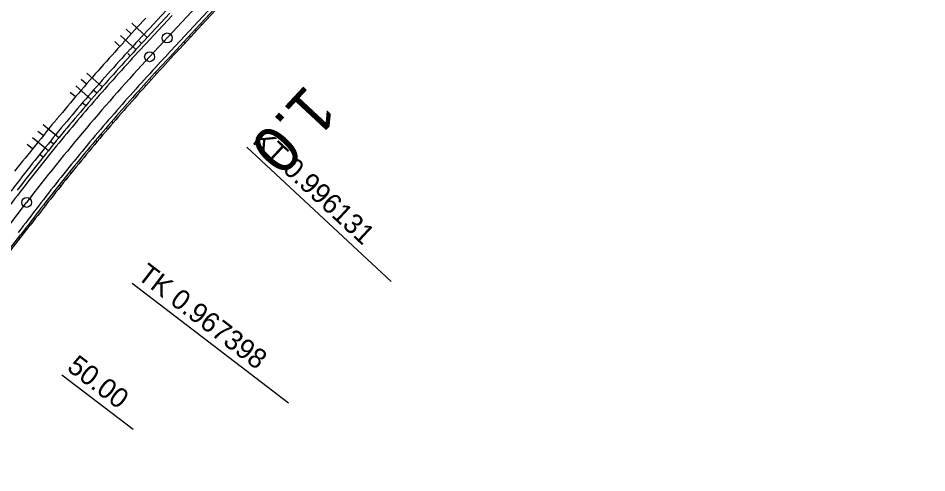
# Model space of a CAD drawing. Extents: x -481645 to -478728, y -1113199 to -1110710.
# Drawn here: x -479251.7 to -479114.8, y -1111118.3 to -1111049.8 of the extents above; entities that cross this region are included whole.
import ezdxf

# ---------------------------------------------------------------- set-up
doc = ezdxf.new("R2010")
doc.units = 0
for name, color, linetype in [('CP14_HATCH_SLOPE_L', 7, 'Continuous'), ('CP1_HECTOMETRY', 7, 'Continuous'), ('O6_HATCH_SLOPE_L', 7, 'Continuous'), ('O6_HATCH_SLOPE_R', 7, 'Continuous'), ('O6_HECTOMETRY', 7, 'Continuous'), ('O6_HLBODY', 7, 'Continuous'), ('O6_HRANA_TELESO', 7, 'Continuous'), ('O6_OSA', 7, 'Continuous'), ('O6_VOZOVKA', 7, 'Continuous'), ('O6_ZPEVKRAJ', 7, 'Continuous')]:
    doc.layers.add(name, color=color, linetype=linetype)

msp = doc.modelspace()

# ---------------------------------------------------------------- linework, layer by layer
at = {"layer": 'CP14_HATCH_SLOPE_L'}
for p, q in [((-479224.18, -1111050.66), (-479224, -1111050.83)), ((-479225.88, -1111052.49), (-479225.7, -1111052.67)), ((-479225.03, -1111051.57), (-479224.94, -1111051.66)), ((-479224.85, -1111051.75), (-479224.85, -1111051.75)), ((-479226.73, -1111053.41), (-479226.64, -1111053.49)), ((-479226.54, -1111053.58), (-479226.54, -1111053.58)), ((-479230.98, -1111057.98), (-479230.78, -1111058.16)), ((-479231.82, -1111058.89), (-479231.72, -1111058.98)), ((-479231.62, -1111059.08), (-479231.62, -1111059.08)), ((-479232.66, -1111059.81), (-479232.45, -1111060)), ((-479233.49, -1111060.73), (-479233.39, -1111060.82)), ((-479233.28, -1111060.92), (-479233.28, -1111060.92)), ((-479237.59, -1111065.38), (-479237.37, -1111065.57)), ((-479239.21, -1111067.27), (-479238.98, -1111067.46)), ((-479238.4, -1111066.32), (-479238.29, -1111066.42)), ((-479238.17, -1111066.52), (-479238.17, -1111066.52)), ((-479240.01, -1111068.21), (-479239.89, -1111068.31)), ((-479239.78, -1111068.41), (-479239.78, -1111068.41)), ((-479243.95, -1111073), (-479243.72, -1111073.19)), ((-479244.73, -1111073.97), (-479244.61, -1111074.06)), ((-479244.5, -1111074.15), (-479244.5, -1111074.15)), ((-479245.5, -1111074.94), (-479245.27, -1111075.12)), ((-479246.27, -1111075.91), (-479246.16, -1111076)), ((-479246.04, -1111076.09), (-479246.04, -1111076.09)), ((-479250.07, -1111080.84), (-479249.86, -1111081)), ((-479250.83, -1111081.83), (-479250.73, -1111081.91)), ((-479250.62, -1111081.99), (-479250.62, -1111081.99)), ((-479251.59, -1111082.82), (-479251.39, -1111082.98))]:
    msp.add_line(p, q, dxfattribs=at)
at = {"layer": 'CP1_HECTOMETRY'}
for p, q in [((-479231.87, -1111055.62), (-478997.26, -1110803.33)), ((-479472.65, -1111367.92), (-479250.4, -1111077.57))]:
    msp.add_line(p, q, dxfattribs=at)
msp.add_arc((-479012.18, -1111259.92), 300, 137.0793, 142.5669, dxfattribs=at)
at = {"layer": 'O6_HATCH_SLOPE_L'}
msp.add_circle((-479229.23, -1111052.79), 0.75, dxfattribs=at)
at = {"layer": 'O6_HATCH_SLOPE_R'}
for p, q in [((-479232.24, -1111052.71), (-479234.56, -1111050.55)), ((-479233.94, -1111054.55), (-479236.26, -1111052.4)), ((-479234.62, -1111052.2), (-479235.41, -1111051.47)), ((-479236.34, -1111054.06), (-479237.12, -1111053.34)), ((-479233.09, -1111053.63), (-479233.46, -1111053.28)), ((-479234.8, -1111055.48), (-479235.17, -1111055.13)), ((-479241.39, -1111059.75), (-479242.18, -1111059.06)), ((-479239.01, -1111060.16), (-479241.35, -1111058.1)), ((-479240.67, -1111062.05), (-479243.01, -1111060.02)), ((-479243.05, -1111061.67), (-479243.84, -1111060.99)), ((-479239.84, -1111061.1), (-479240.22, -1111060.77)), ((-479241.49, -1111063.01), (-479241.87, -1111062.68)), ((-479245.54, -1111067.83), (-479247.9, -1111065.88)), ((-479247.92, -1111067.51), (-479248.71, -1111066.87)), ((-479249.51, -1111069.49), (-479250.31, -1111068.85)), ((-479247.13, -1111069.78), (-479249.51, -1111067.85)), ((-479246.34, -1111068.8), (-479246.73, -1111068.48)), ((-479247.92, -1111070.76), (-479248.32, -1111070.44))]:
    msp.add_line(p, q, dxfattribs=at)
at = {"layer": 'O6_HECTOMETRY'}
for p, q in [((-479217.22, -1111069.24), (-479195.47, -1111089.47)), ((-479234.52, -1111089.72), (-479210.93, -1111107.78))]:
    msp.add_line(p, q, dxfattribs=at)
for centre in [(-479231.87, -1111055.62), (-479250.4, -1111077.57)]:
    msp.add_circle(centre, 0.75, dxfattribs=at)
at = {"layer": 'O6_HLBODY'}
msp.add_line((-479245.09, -1111103.54), (-479234.37, -1111111.74), dxfattribs=at)
at = {"layer": 'O6_HRANA_TELESO'}
msp.add_line((-479231.37, -1111050.8), (-479227.97, -1111047.14), dxfattribs=at)
for centre, radius, start, end in [((-479122.13, -1111155.72), 151.46, 136.156, 138.0517), ((-479012.18, -1111259.92), 302.92, 137.2952, 138.2501), ((-479012.18, -1111259.92), 302.92, 138.2501, 139.2051), ((-479012.18, -1111259.92), 302.92, 139.2051, 140.16), ((-479012.18, -1111259.92), 302.92, 140.16, 141.1149), ((-479012.18, -1111259.92), 302.92, 141.1149, 142.0699), ((-478532.29, -1111629.71), 908.75, 142.27851, 142.59535)]:
    msp.add_arc(centre, radius, start, end, dxfattribs=at)
at = {"layer": 'O6_OSA'}
for p, q in [((-479224, -1111050.83), (-479220.6, -1111047.16)), ((-479227.39, -1111054.5), (-479224, -1111050.83)), ((-479252.91, -1111084.96), (-479249.86, -1111081))]:
    msp.add_line(p, q, dxfattribs=at)
for centre, radius, start, end in [((-479122.26, -1111154.77), 152.18, 136.3891, 138.2779), ((-479011.31, -1111258.96), 304.34, 137.5391, 138.4941), ((-479119.92, -1111157.32), 148.74, 136.2679, 138.1904), ((-479011.26, -1111258.86), 304.32, 138.5136, 139.4685), ((-479011.66, -1111259.34), 297.47, 137.4446, 138.3995), ((-479011.43, -1111259.03), 304.3, 139.4246, 140.3796), ((-479011.83, -1111259.52), 297.46, 138.3527, 139.3077), ((-479011.62, -1111259.23), 304.28, 140.3274, 141.2824), ((-479011.84, -1111259.51), 297.45, 139.3068, 140.2618), ((-479013.18, -1111261.17), 304.29, 140.814, 141.769), ((-479012.45, -1111260.25), 297.45, 140.0777, 141.0327), ((-479012.75, -1111260.64), 297.46, 140.9378, 141.8927), ((-478543, -1111625.73), 892.4, 142.06107, 142.38068)]:
    msp.add_arc(centre, radius, start, end, dxfattribs=at)
at = {"layer": 'O6_VOZOVKA'}
for p, q in [((-479225.9, -1111051.78), (-479222.5, -1111048.11)), ((-479231.87, -1111053.05), (-479228.47, -1111049.39)), ((-479229.31, -1111055.44), (-479225.9, -1111051.78))]:
    msp.add_line(p, q, dxfattribs=at)
for centre, radius, start, end in [((-479122.77, -1111157.27), 150.88, 136.313, 138.2188), ((-479121.48, -1111158.45), 149.12, 136.308, 138.2221), ((-479012.18, -1111259.92), 301.75, 137.6756, 138.6306), ((-479012.18, -1111259.92), 298.25, 137.6756, 138.6306), ((-479012.18, -1111259.92), 301.75, 138.6306, 139.5855), ((-479012.18, -1111259.92), 298.25, 138.6306, 139.5855), ((-479012.18, -1111259.92), 301.75, 139.5855, 140.5404), ((-479012.18, -1111259.92), 298.25, 139.5855, 140.5404), ((-479012.18, -1111259.92), 301.75, 140.5404, 141.4954), ((-479012.18, -1111259.92), 298.25, 140.5404, 141.4954), ((-479012.18, -1111259.92), 301.75, 141.4954, 142.4503), ((-479012.18, -1111259.92), 298.25, 141.4954, 142.4503), ((-478534.18, -1111628.33), 905.25, 142.40137, 142.71806), ((-478539.74, -1111624.08), 894.75, 142.39981, 142.71976)]:
    msp.add_arc(centre, radius, start, end, dxfattribs=at)
at = {"layer": 'O6_ZPEVKRAJ'}
for p, q in [((-479232.24, -1111052.71), (-479228.83, -1111049.05)), ((-479225.54, -1111052.12), (-479222.13, -1111048.46)), ((-479228.94, -1111055.78), (-479225.54, -1111052.12)), ((-479254.32, -1111086.39), (-479251.28, -1111082.42))]:
    msp.add_line(p, q, dxfattribs=at)
for centre, radius, start, end in [((-479122.95, -1111157.1), 151.12, 136.3137, 138.2183), ((-479012.18, -1111259.92), 302.25, 137.6756, 138.6306), ((-479121.3, -1111158.62), 148.88, 136.3073, 138.2226), ((-479012.18, -1111259.92), 302.25, 138.6306, 139.5855), ((-479012.18, -1111259.92), 297.75, 137.6756, 138.6306), ((-479012.18, -1111259.92), 297.75, 138.6306, 139.5855), ((-479012.18, -1111259.92), 302.25, 139.5855, 140.5404), ((-479012.18, -1111259.92), 297.75, 139.5855, 140.5404), ((-479012.18, -1111259.92), 302.25, 140.5404, 141.4954), ((-479012.18, -1111259.92), 297.75, 140.5404, 141.4954), ((-479012.18, -1111259.92), 302.25, 141.4954, 142.4503), ((-479012.18, -1111259.92), 297.75, 141.4954, 142.4503), ((-478540.53, -1111623.47), 893.25, 142.39959, 142.72001)]:
    msp.add_arc(centre, radius, start, end, dxfattribs=at)

# ---------------------------------------------------------------- texts
at = {"layer": 'O6_HATCH_SLOPE_L'}
msp.add_text('1.0', height=7, rotation=227.0337, dxfattribs=at).set_placement((-479208.24, -1111059.59))
at = {"layer": 'O6_HECTOMETRY'}
for s, rotation, p in [('KT 0.996131', 317.0793, (-479216.54, -1111068.51)), ('TK 0.967398', 322.5669, (-479233.91, -1111088.93))]:
    msp.add_text(s, height=2.999, rotation=rotation, dxfattribs=at).set_placement(p)
at = {"layer": 'O6_HLBODY'}
msp.add_text('50.00', height=3, rotation=322.5669, dxfattribs=at).set_placement((-479244.49, -1111102.74))

doc.saveas('drawing.dxf')
